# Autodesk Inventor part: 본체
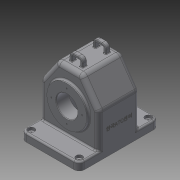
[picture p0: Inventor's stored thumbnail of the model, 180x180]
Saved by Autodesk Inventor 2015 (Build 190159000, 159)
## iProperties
Created: 2016-12
Part Number: 본체
Material: 일반
Document SubType Name: Modeling
Designer: owner
Density: 1 g/cm^3
Appearance: 기본값
Mass: 393.646 g
Surface Area: 1138.68 cm^2
Volume: 393.646 cm^3
Author: owner
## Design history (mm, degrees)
sketch "스케치1"
  geometry: L1 (55, -65)-(-55, -65); L2 (-55, -65)-(-55, 15); L3 (-55, 15)-(-23.491, 60); L4 (-23.491, 60)-(23.491, 60); L5 (23.491, 60)-(55, 15); L6 (55, 15)-(55, -65); 2 further points
  constraints: 12 end point, 2 parallel, 1 horizontal, 1 midpoint, 1 perpendicular, 1 vertical alignment
  dimensions: "d0" = 35 deg angle of L2 L3; "d1" = 35 deg angle of L6 L5; "d2" = 110 distance of L1.start L1.end; "d3" = 65 distance from line of L1 point (0, 0); "d5" = 80 distance of L1.end L2.end; "d6" = 80 distance from line of L1 L5.end; "d8" = 125 distance between parallel lines of L1 L4
extrude "돌출1" new body sketch "스케치1" stored distance "d9" = 77; taper "d10" = 0 deg
sketch "스케치2"
  geometry: L1 (110, -77)-(110, 0) reference; L2 (0, 0)-(110, 0) reference; L3 (0, 0)-(0, -77) reference; L4 (110, -77)-(0, -77) reference; L5 (0, 36.5)-(110, 36.5); L6 (110, 36.5)-(110, -113.5); L7 (110, -113.5)-(0, -113.5); L8 (0, -113.5)-(0, 36.5); L9 (0, 36.5)-(110, -113.5); L10 (110, 36.5)-(0, -113.5); 1 further point
  constraints: 12 end point, 2 midpoint, 2 parallel, 1 horizontal, 1 perpendicular
  dimensions: "d11" = 110 distance of L6.end L7.end; "d12" = 150 distance of L5.end L6.end
extrude "돌출2" join sketch "스케치2" distance "d13" = 15; taper "d14" = 0 deg
sketch "스케치3"
  geometry: C1 r 37.5 at (0, 0); 1 further point
  constraints: 1 centre point, 1 coincident
  dimensions: "d15" = 75 diameter of C1
extrude "돌출3" join sketch "스케치3" distance "d16" = 5; taper "d17" = 0 deg
sketch "스케치4"
  geometry: C1 r 31 at (0, 0); 1 further point
  constraints: 1 centre point, 1 coincident
  dimensions: "d18" = 62 diameter of C1
extrude "돌출4" join sketch "스케치4" distance "d19" = 10; taper "d20" = 0 deg
sketch "스케치5"
  geometry: L1 (-55, -65)-(-55, 15) reference; L2 (-55, 15)-(-23.491, 60) reference; L3 (-23.491, 60)-(23.491, 60) reference; L4 (23.491, 60)-(55, 15) reference; L5 (55, 15)-(55, -65) reference; L6 (55, -65)-(-55, -65) reference; L7 (-20.888, 55)-(-50, 13.424); L8 (-50, 13.424)-(-50, -65); L9 (50, -65)-(50, 13.424); L10 (50, 13.424)-(20.888, 55); L11 (20.888, 55)-(-20.888, 55); 1 further point
  constraints: 10 end point, 2 point on line, 3 other
  dimensions: "d21" = 5 distance between parallel lines of L1 L8; "d22" = 5 distance between parallel lines of L5 L9
extrude "돌출5" cut sketch "스케치5" stored distance "d23" = 67; taper "d24" = 0 deg
sketch "스케치6"
  geometry: L1 (60, 38.5)-(15, 38.5) reference; L2 (55, 33.5)-(13.424, 33.5) reference; L3 (0, 105)-(0, -105) reference; L4 (-37.5, 38.5)-(37.5, 38.5) reference; L5 (0, 19.5)-(27, 19.5); L6 (27, 19.5)-(41, 33.5); L7 (41, 33.5)-(0, 33.5); L8 (37.5, 43.5)-(-37.5, 43.5) reference; 1 further point
  constraints: 6 end point, 2 point on line, 1 parallel, 1 perpendicular
  dimensions: "d25" = 24 distance between parallel lines of L8 L5; "d26" = 45 deg angle of L5 L6; "d27" = 5 distance between parallel lines of L1 L7; "d28" = 27 distance of L5.start L5.end
revolve "회전1" sketch "스케치6" stored, may be unused: angle "d29" = 90 deg
sketch "스케치7"
  geometry: C1 r 37.5 at (0, 0) reference; C2 r 20 at (0, 0)
  constraints: 1 centre point, 1 coincident
  dimensions: "d30" = 40 diameter of C2
extrude "돌출6" cut sketch "스케치7" stored distance "d31" = 67; taper "d32" = 0 deg
node "작업 평면1"
sketch "스케치8"
  geometry: L1 (23.491, 60)-(-23.491, 60) reference; L2 (-55, -50)-(55, -50) reference; L3 (55, -50)-(55, 15) reference; L4 (55, 15)-(23.491, 60) reference; L5 (23.491, 60)-(-23.491, 60) reference; L6 (-23.491, 60)-(-55, 15) reference; L7 (-55, 15)-(-55, -50) reference; L8 (-12.5, 60)-(-12.5, 75); L9 (-12.5, 75)-(12.5, 75); L10 (12.5, 75)-(12.5, 60); L11 (7.5, 60)-(7.5, 70); L12 (7.5, 70)-(-7.5, 70); L13 (-7.5, 70)-(-7.5, 60); L14 (50, -65)-(-50, -65) reference; C1 r 37.5 at (0, 0) reference; 2 further points
  constraints: 12 end point, 4 perpendicular, 4 point on line, 2 parallel, 1 midpoint, 1 vertical alignment
  dimensions: "d34" = 25 distance of L8.end L9.end; "d35" = 15 distance between parallel lines of L11 L13; "d36" = 5 distance between parallel lines of L13 L8; "d38" = 140 distance between parallel lines of L14 L9; "d39" = 5 distance between parallel lines of L9 L12
extrude "돌출7" join sketch "스케치8" distance "d40" = 8; taper "d41" = 0 deg
fillet "모깎기1" dims "d42" = 8
fillet "모깎기2" dims "d43" = 1
fillet "모깎기3" dims "d44" = 1
fillet "모깎기4" dims "d45" = 10
sketch "스케치9"
  geometry: A1 r 10 centre (10, 103.5) between (10, 113.5) and (0, 103.5) reference; A2 r 10 centre (100, 103.5) between (110, 103.5) and (100, 113.5) reference; A3 r 10 centre (10, -26.5) between (0, -26.5) and (10, -36.5) reference; A4 r 10 centre (100, -26.5) between (100, -36.5) and (110, -26.5) reference; 5 further points
  constraints: 4 coincident
hole "구멍1" sketch "스케치9" at (10, 103.5), (100, 103.5), (100, -26.5), (10, -26.5) diameter "d46" = 5; stored, may be unused: countersink angle "d50" = 90 deg, drill point angle "d52" = 118 deg; dims "d47" = 6, "d48" = 12, "d49" = 5, "d51" = 8
sketch "스케치10"
  geometry: C1 r 20 at (0, 0) reference; 1 further point
  constraints: 1 vertical alignment
  dimensions: "d53" = 29 distance of point (0, 29) C1.centre
hole "구멍2" sketch "스케치10" at (0, 29) diameter "d54" = 2.459; stored, may be unused: countersink angle "d58" = 90 deg, drill point angle "d60" = 118 deg; dims "d55" = 6, "d56" = 4, "d57" = 2, "d59" = 8
sketch "스케치11"
  geometry: C1 r 20 at (0, 0) reference; 1 further point
  constraints: 1 vertical alignment
  dimensions: "d64" = 26 distance of C1.centre point (0, 26)
hole "구멍3" sketch "스케치11" at (0, 26) diameter "d65" = 2.459; stored, may be unused: countersink angle "d69" = 90 deg, drill point angle "d71" = 118 deg; dims "d66" = 6, "d67" = 4, "d68" = 2, "d70" = 8
fillet "모깎기5" dims "d75" = 10
fillet "모깎기6" dims "d76" = 8
fillet "모깎기7" dims "d77" = 3
fillet "모깎기8" dims "d78" = 3
fillet "모깎기9" dims "d79" = 3
fillet "모깎기10" dims "d80" = 1
fillet "모깎기11" dims "d81" = 3
chamfer "모따기1" distance "d82" = 1; stored, may be unused: second distance "d83" = 2, angle "d84" = 45 deg
fillet "모깎기12" dims "d85" = 3
fillet "모깎기13" dims "d86" = 3
fillet "모깎기14" dims "d87" = 3
node "작업 평면2"
sketch "스케치12"
  geometry: L1 (11.847, 38.5)-(-47, 38.5) reference; L2 (-65, -65)-(-65, 65) reference; 2 further points
  constraints: 1 other
  dimensions: "d89" = 38.5 distance from line of point (-20, 0) L1; "d90" = 45 distance from line of point (-20, 0) L2
feature "엠보싱1" sketch "스케치12" dims "d0" = 35 deg, "d1" = 35 deg, "d2" = 110, "d3" = 65, "d5" = 80, "d6" = 80, "d8" = 125, "d11" = 110, "d12" = 150, "d91" = 0.5, "d92" = 0
fillet "모깎기15" dims "d93" = 1
fillet "모깎기16" dims "d94" = 1
node "솔리드1"
mirror "대칭1"
pattern_circular "원형 패턴1" dims angle "d62" = 360 deg
pattern_circular "원형 패턴2" dims angle "d73" = 360 deg
node "투영된 루프1"
node "절단 모서리 투영1"
other parameters: "d33" = 26, "d88" = 94.25
